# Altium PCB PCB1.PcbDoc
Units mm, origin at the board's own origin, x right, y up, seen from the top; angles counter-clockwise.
Board outline 152.4 x 101.6 mm, 2 copper layers (Top Layer, Bottom Layer); 306 components, 275 nets, 612 pads, 0 vias.
Unrouted connection lines stored in the file: 337.
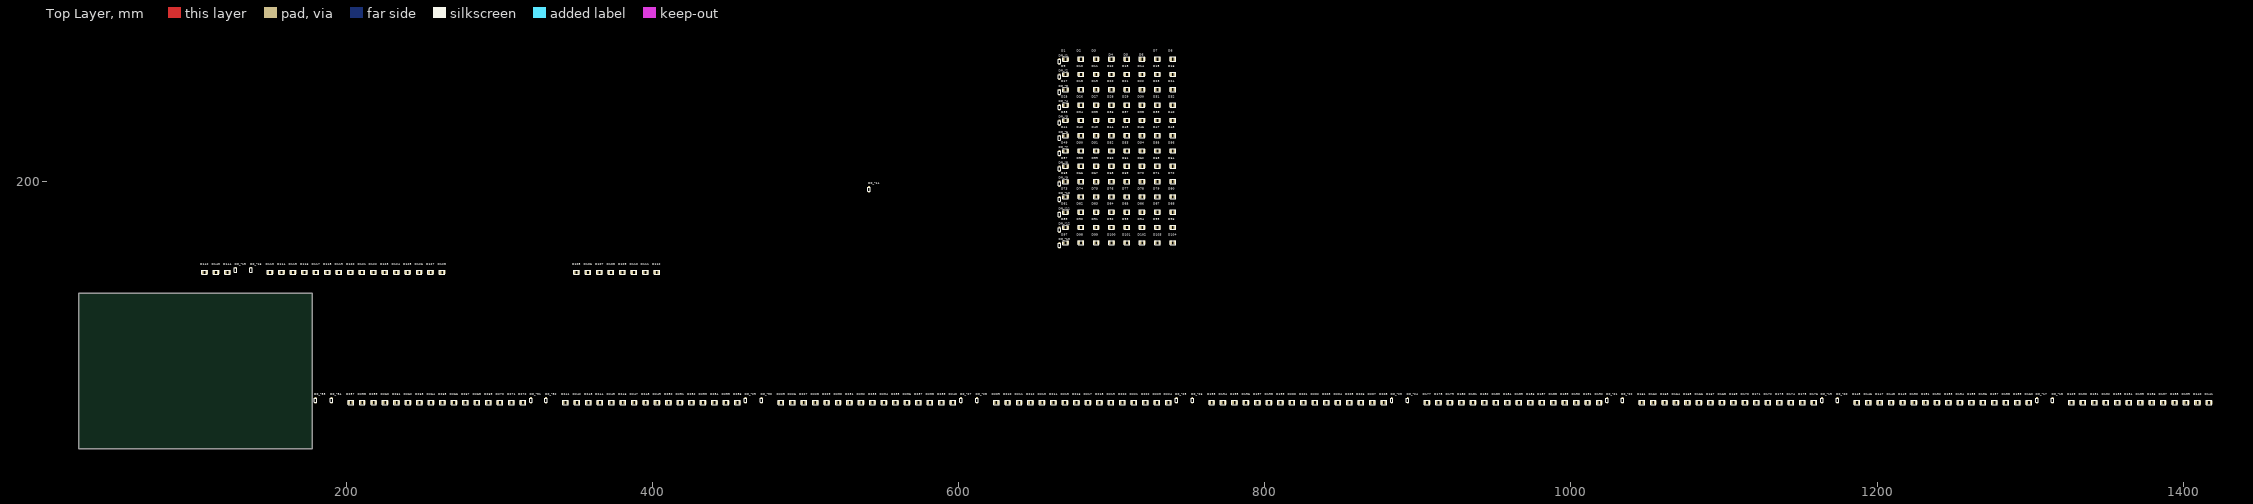
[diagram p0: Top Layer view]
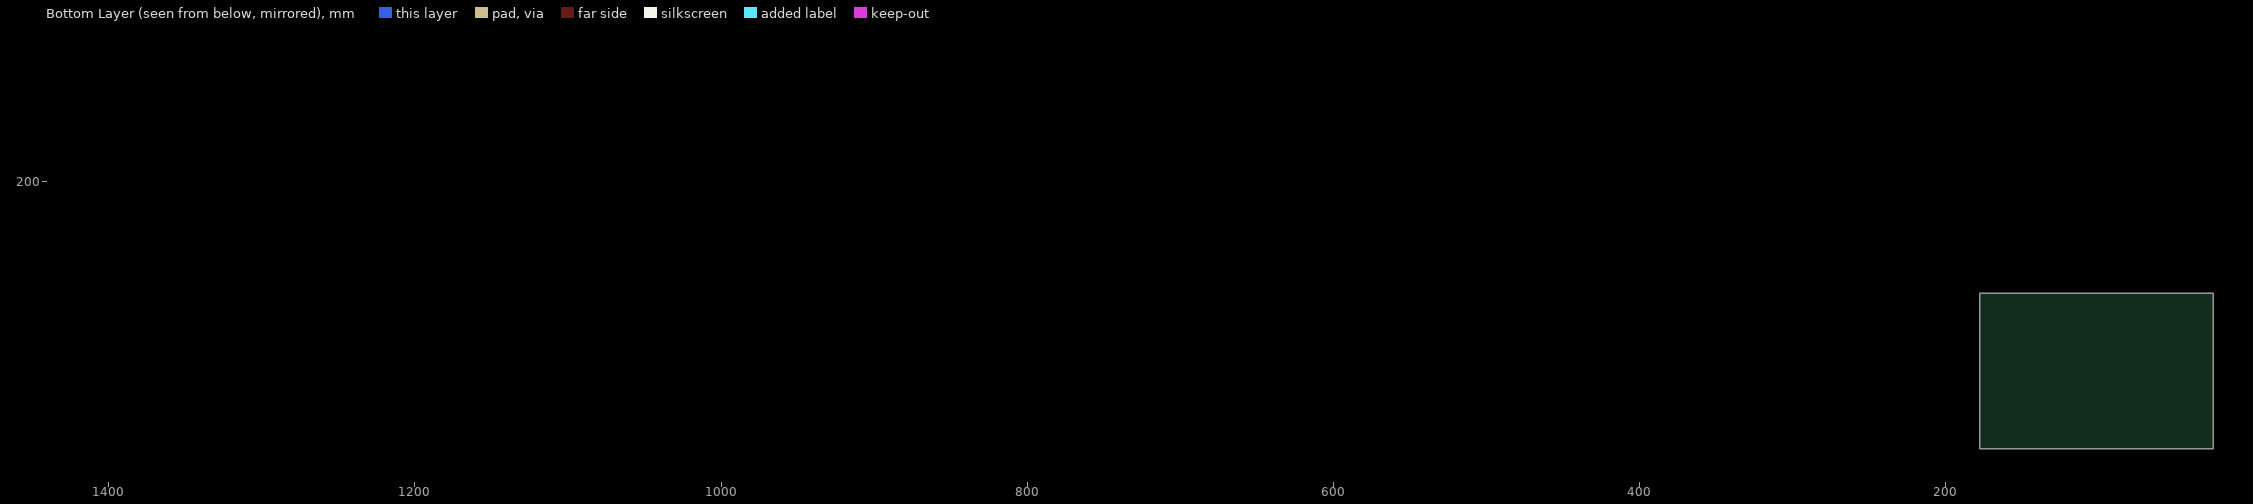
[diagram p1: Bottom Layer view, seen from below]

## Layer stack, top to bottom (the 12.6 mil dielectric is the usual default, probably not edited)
Top Solder: solder mask 0.0102, Solder Resist, Dk 3.5
Top Layer: signal copper 0.0356
Dielectric 1: dielectric 0.32, FR-4, Dk 4.8
Bottom Layer: signal copper 0.0356
Bottom Solder: solder mask 0.0102, Solder Resist, Dk 3.5

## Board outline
25.4,25.4 177.8,25.4 177.8,127 25.4,127

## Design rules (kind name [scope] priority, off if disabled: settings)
Clearance [All] p1: gap=0.254
PolygonConnect [All] p1: connectstyle=Relief reliefconductorwidth=0.254 reliefentries=4 polygonreliefangle="90 Angle" airgapwidth=0.254
RoutingVias [All] p1: holewidth=0.711 width=1.27 viastyle="Through Hole" minholewidth=0.711 minwidth=1.27 maxholewidth=0.711 maxwidth=1.27
SolderMaskExpansion [All] p1: expansion=0.102
Width [All] p1: maxlimit=0.254 minlimit=0.254 preferedwidth=0.254
30 further rules are at their usual default settings.

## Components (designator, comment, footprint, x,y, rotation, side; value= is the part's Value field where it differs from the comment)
D1 "LED0" UV_LED 670,280 r0 top
D2 "LED0" UV_LED 680,280 r0 top
D3 "LED0" UV_LED 690,280 r0 top
D4 "LED0" UV_LED 700,280 r0 top
D5 "LED0" UV_LED 710,280 r0 top
D6 "LED0" UV_LED 720,280 r0 top
D7 "LED0" UV_LED 730,280 r0 top
D8 "LED0" UV_LED 740,280 r0 top
D9 "LED0" UV_LED 670,270 r0 top
D10 "LED0" UV_LED 680,270 r0 top
D11 "LED0" UV_LED 690,270 r0 top
D12 "LED0" UV_LED 700,270 r0 top
D13 "LED0" UV_LED 710,270 r0 top
D14 "LED0" UV_LED 720,270 r0 top
D15 "LED0" UV_LED 730,270 r0 top
D16 "LED0" UV_LED 740,270 r0 top
D17 "LED0" UV_LED 670,260 r0 top
D18 "LED0" UV_LED 680,260 r0 top
D19 "LED0" UV_LED 690,260 r0 top
D20 "LED0" UV_LED 700,260 r0 top
D21 "LED0" UV_LED 710,260 r0 top
D22 "LED0" UV_LED 720,260 r0 top
D23 "LED0" UV_LED 730,260 r0 top
D24 "LED0" UV_LED 740,260 r0 top
D25 "LED0" UV_LED 670,250 r0 top
D26 "LED0" UV_LED 680,250 r0 top
D27 "LED0" UV_LED 690,250 r0 top
D28 "LED0" UV_LED 700,250 r0 top
D29 "LED0" UV_LED 710,250 r0 top
D30 "LED0" UV_LED 720,250 r0 top
D31 "LED0" UV_LED 730,250 r0 top
D32 "LED0" UV_LED 740,250 r0 top
D33 "LED0" UV_LED 670,240 r0 top
D34 "LED0" UV_LED 680,240 r0 top
D35 "LED0" UV_LED 690,240 r0 top
D36 "LED0" UV_LED 700,240 r0 top
D37 "LED0" UV_LED 710,240 r0 top
D38 "LED0" UV_LED 720,240 r0 top
D39 "LED0" UV_LED 730,240 r0 top
D40 "LED0" UV_LED 740,240 r0 top
D41 "LED0" UV_LED 670,230 r0 top
D42 "LED0" UV_LED 680,230 r0 top
D43 "LED0" UV_LED 690,230 r0 top
D44 "LED0" UV_LED 700,230 r0 top
D45 "LED0" UV_LED 710,230 r0 top
D46 "LED0" UV_LED 720,230 r0 top
D47 "LED0" UV_LED 730,230 r0 top
D48 "LED0" UV_LED 740,230 r0 top
D49 "LED0" UV_LED 670,220 r0 top
D50 "LED0" UV_LED 680,220 r0 top
D51 "LED0" UV_LED 690,220 r0 top
D52 "LED0" UV_LED 700,220 r0 top
D53 "LED0" UV_LED 710,220 r0 top
D54 "LED0" UV_LED 720,220 r0 top
D55 "LED0" UV_LED 730,220 r0 top
D56 "LED0" UV_LED 740,220 r0 top
D57 "LED0" UV_LED 670,210 r0 top
D58 "LED0" UV_LED 680,210 r0 top
D59 "LED0" UV_LED 690,210 r0 top
D60 "LED0" UV_LED 700,210 r0 top
D61 "LED0" UV_LED 710,210 r0 top
D62 "LED0" UV_LED 720,210 r0 top
D63 "LED0" UV_LED 730,210 r0 top
D64 "LED0" UV_LED 740,210 r0 top
D65 "LED0" UV_LED 670,200 r0 top
D66 "LED0" UV_LED 680,200 r0 top
D67 "LED0" UV_LED 690,200 r0 top
D68 "LED0" UV_LED 700,200 r0 top
D69 "LED0" UV_LED 710,200 r0 top
D70 "LED0" UV_LED 720,200 r0 top
D71 "LED0" UV_LED 730,200 r0 top
D72 "LED0" UV_LED 740,200 r0 top
D73 "LED0" UV_LED 670,190 r0 top
D74 "LED0" UV_LED 680,190 r0 top
D75 "LED0" UV_LED 690,190 r0 top
D76 "LED0" UV_LED 700,190 r0 top
D77 "LED0" UV_LED 710,190 r0 top
D78 "LED0" UV_LED 720,190 r0 top
D79 "LED0" UV_LED 730,190 r0 top
D80 "LED0" UV_LED 740,190 r0 top
D81 "LED0" UV_LED 670,180 r0 top
D82 "LED0" UV_LED 680,180 r0 top
D83 "LED0" UV_LED 690,180 r0 top
D84 "LED0" UV_LED 700,180 r0 top
D85 "LED0" UV_LED 710,180 r0 top
D86 "LED0" UV_LED 720,180 r0 top
D87 "LED0" UV_LED 730,180 r0 top
D88 "LED0" UV_LED 740,180 r0 top
D89 "LED0" UV_LED 670,170 r0 top
D90 "LED0" UV_LED 680,170 r0 top
D91 "LED0" UV_LED 690,170 r0 top
D92 "LED0" UV_LED 700,170 r0 top
D93 "LED0" UV_LED 710,170 r0 top
D94 "LED0" UV_LED 720,170 r0 top
D95 "LED0" UV_LED 730,170 r0 top
D96 "LED0" UV_LED 740,170 r0 top
D97 "LED0" UV_LED 670,160 r0 top
D98 "LED0" UV_LED 680,160 r0 top
D99 "LED0" UV_LED 690,160 r0 top
D100 "LED0" UV_LED 700,160 r0 top
D101 "LED0" UV_LED 710,160 r0 top
D102 "LED0" UV_LED 720,160 r0 top
D103 "LED0" UV_LED 730,160 r0 top
D104 "LED0" UV_LED 740,160 r0 top
D105 "LED0" UV_LED 350.52,140.716 r0 top
D106 "LED0" UV_LED 358.013,140.716 r0 top
D107 "LED0" UV_LED 365.506,140.716 r0 top
D108 "LED0" UV_LED 372.999,140.716 r0 top
D109 "LED0" UV_LED 380.492,140.716 r0 top
D110 "LED0" UV_LED 387.985,140.716 r0 top
D111 "LED0" UV_LED 395.478,140.716 r0 top
D112 "LED0" UV_LED 402.971,140.716 r0 top
D113 "LED0" UV_LED 150.368,140.716 r0 top
D114 "LED0" UV_LED 157.861,140.716 r0 top
D115 "LED0" UV_LED 165.354,140.716 r0 top
D116 "LED0" UV_LED 172.847,140.716 r0 top
D117 "LED0" UV_LED 180.34,140.716 r0 top
D118 "LED0" UV_LED 187.833,140.716 r0 top
D119 "LED0" UV_LED 195.326,140.716 r0 top
D120 "LED0" UV_LED 202.819,140.716 r0 top
D121 "LED0" UV_LED 210.312,140.716 r0 top
D122 "LED0" UV_LED 217.805,140.716 r0 top
D123 "LED0" UV_LED 225.298,140.716 r0 top
D124 "LED0" UV_LED 232.791,140.716 r0 top
D125 "LED0" UV_LED 240.284,140.716 r0 top
D126 "LED0" UV_LED 247.777,140.716 r0 top
D127 "LED0" UV_LED 255.27,140.716 r0 top
D128 "LED0" UV_LED 262.763,140.716 r0 top
D129 "LED0" UV_LED 1327.023,55.626 r0 top
D130 "LED0" UV_LED 1334.516,55.626 r0 top
D131 "LED0" UV_LED 1342.009,55.626 r0 top
D132 "LED0" UV_LED 1349.502,55.626 r0 top
D133 "LED0" UV_LED 1356.995,55.626 r0 top
D134 "LED0" UV_LED 1364.488,55.626 r0 top
D135 "LED0" UV_LED 1371.981,55.626 r0 top
D136 "LED0" UV_LED 1379.474,55.626 r0 top
D137 "LED0" UV_LED 1386.967,55.626 r0 top
D138 "LED0" UV_LED 1394.46,55.626 r0 top
D139 "LED0" UV_LED 1401.953,55.626 r0 top
D140 "LED0" UV_LED 1409.446,55.626 r0 top
D141 "LED0" UV_LED 1416.939,55.626 r0 top
D142 "LED0" UV_LED 107.569,140.716 r0 top
D143 "LED0" UV_LED 115.062,140.716 r0 top
D144 "LED0" UV_LED 122.555,140.716 r0 top
D145 "LED0" UV_LED 1186.815,55.626 r0 top
D146 "LED0" UV_LED 1194.308,55.626 r0 top
D147 "LED0" UV_LED 1201.801,55.626 r0 top
D148 "LED0" UV_LED 1209.294,55.626 r0 top
D149 "LED0" UV_LED 1216.787,55.626 r0 top
D150 "LED0" UV_LED 1224.28,55.626 r0 top
D151 "LED0" UV_LED 1231.773,55.626 r0 top
D152 "LED0" UV_LED 1239.266,55.626 r0 top
D153 "LED0" UV_LED 1246.759,55.626 r0 top
D154 "LED0" UV_LED 1254.252,55.626 r0 top
D155 "LED0" UV_LED 1261.745,55.626 r0 top
D156 "LED0" UV_LED 1269.238,55.626 r0 top
D157 "LED0" UV_LED 1276.731,55.626 r0 top
D158 "LED0" UV_LED 1284.224,55.626 r0 top
D159 "LED0" UV_LED 1291.717,55.626 r0 top
D160 "LED0" UV_LED 1299.21,55.626 r0 top
D161 "LED0" UV_LED 1046.353,55.626 r0 top
D162 "LED0" UV_LED 1053.846,55.626 r0 top
D163 "LED0" UV_LED 1061.339,55.626 r0 top
D164 "LED0" UV_LED 1068.832,55.626 r0 top
D165 "LED0" UV_LED 1076.325,55.626 r0 top
D166 "LED0" UV_LED 1083.818,55.626 r0 top
D167 "LED0" UV_LED 1091.311,55.626 r0 top
D168 "LED0" UV_LED 1098.804,55.626 r0 top
D169 "LED0" UV_LED 1106.297,55.626 r0 top
D170 "LED0" UV_LED 1113.79,55.626 r0 top
D171 "LED0" UV_LED 1121.283,55.626 r0 top
D172 "LED0" UV_LED 1128.776,55.626 r0 top
D173 "LED0" UV_LED 1136.269,55.626 r0 top
D174 "LED0" UV_LED 1143.762,55.626 r0 top
D175 "LED0" UV_LED 1151.255,55.626 r0 top
D176 "LED0" UV_LED 1158.748,55.626 r0 top
D177 "LED0" UV_LED 906.145,55.626 r0 top
D178 "LED0" UV_LED 913.638,55.626 r0 top
D179 "LED0" UV_LED 921.131,55.626 r0 top
D180 "LED0" UV_LED 928.624,55.626 r0 top
D181 "LED0" UV_LED 936.117,55.626 r0 top
D182 "LED0" UV_LED 943.61,55.626 r0 top
D183 "LED0" UV_LED 951.103,55.626 r0 top
D184 "LED0" UV_LED 958.596,55.626 r0 top
D185 "LED0" UV_LED 966.089,55.626 r0 top
D186 "LED0" UV_LED 973.582,55.626 r0 top
D187 "LED0" UV_LED 981.075,55.626 r0 top
D188 "LED0" UV_LED 988.568,55.626 r0 top
D189 "LED0" UV_LED 996.061,55.626 r0 top
D190 "LED0" UV_LED 1003.554,55.626 r0 top
D191 "LED0" UV_LED 1011.047,55.626 r0 top
D192 "LED0" UV_LED 1018.54,55.626 r0 top
D193 "LED0" UV_LED 765.429,55.626 r0 top
D194 "LED0" UV_LED 772.922,55.626 r0 top
D195 "LED0" UV_LED 780.415,55.626 r0 top
D196 "LED0" UV_LED 787.908,55.626 r0 top
D197 "LED0" UV_LED 795.401,55.626 r0 top
D198 "LED0" UV_LED 802.894,55.626 r0 top
D199 "LED0" UV_LED 810.387,55.626 r0 top
D200 "LED0" UV_LED 817.88,55.626 r0 top
D201 "LED0" UV_LED 825.373,55.626 r0 top
D202 "LED0" UV_LED 832.866,55.626 r0 top
D203 "LED0" UV_LED 840.359,55.626 r0 top
D204 "LED0" UV_LED 847.852,55.626 r0 top
D205 "LED0" UV_LED 855.345,55.626 r0 top
D206 "LED0" UV_LED 862.838,55.626 r0 top
D207 "LED0" UV_LED 870.331,55.626 r0 top
D208 "LED0" UV_LED 877.824,55.626 r0 top
D209 "LED0" UV_LED 624.713,55.626 r0 top
D210 "LED0" UV_LED 632.206,55.626 r0 top
D211 "LED0" UV_LED 639.699,55.626 r0 top
D212 "LED0" UV_LED 647.192,55.626 r0 top
D213 "LED0" UV_LED 654.685,55.626 r0 top
D214 "LED0" UV_LED 662.178,55.626 r0 top
D215 "LED0" UV_LED 669.671,55.626 r0 top
D216 "LED0" UV_LED 677.164,55.626 r0 top
D217 "LED0" UV_LED 684.657,55.626 r0 top
D218 "LED0" UV_LED 692.15,55.626 r0 top
D219 "LED0" UV_LED 699.643,55.626 r0 top
D220 "LED0" UV_LED 707.136,55.626 r0 top
D221 "LED0" UV_LED 714.629,55.626 r0 top
D222 "LED0" UV_LED 722.122,55.626 r0 top
D223 "LED0" UV_LED 729.615,55.626 r0 top
D224 "LED0" UV_LED 737.108,55.626 r0 top
D225 "LED0" UV_LED 483.997,55.626 r0 top
D226 "LED0" UV_LED 491.49,55.626 r0 top
D227 "LED0" UV_LED 498.983,55.626 r0 top
D228 "LED0" UV_LED 506.476,55.626 r0 top
D229 "LED0" UV_LED 513.969,55.626 r0 top
D230 "LED0" UV_LED 521.462,55.626 r0 top
D231 "LED0" UV_LED 528.955,55.626 r0 top
D232 "LED0" UV_LED 536.448,55.626 r0 top
D233 "LED0" UV_LED 543.941,55.626 r0 top
D234 "LED0" UV_LED 551.434,55.626 r0 top
D235 "LED0" UV_LED 558.927,55.626 r0 top
D236 "LED0" UV_LED 566.42,55.626 r0 top
D237 "LED0" UV_LED 573.913,55.626 r0 top
D238 "LED0" UV_LED 581.406,55.626 r0 top
D239 "LED0" UV_LED 588.899,55.626 r0 top
D240 "LED0" UV_LED 596.392,55.626 r0 top
D241 "LED0" UV_LED 343.281,55.626 r0 top
D242 "LED0" UV_LED 350.774,55.626 r0 top
D243 "LED0" UV_LED 358.267,55.626 r0 top
D244 "LED0" UV_LED 365.76,55.626 r0 top
D245 "LED0" UV_LED 373.253,55.626 r0 top
D246 "LED0" UV_LED 380.746,55.626 r0 top
D247 "LED0" UV_LED 388.239,55.626 r0 top
D248 "LED0" UV_LED 395.732,55.626 r0 top
D249 "LED0" UV_LED 403.225,55.626 r0 top
D250 "LED0" UV_LED 410.718,55.626 r0 top
D251 "LED0" UV_LED 418.211,55.626 r0 top
D252 "LED0" UV_LED 425.704,55.626 r0 top
D253 "LED0" UV_LED 433.197,55.626 r0 top
D254 "LED0" UV_LED 440.69,55.626 r0 top
D255 "LED0" UV_LED 448.183,55.626 r0 top
D256 "LED0" UV_LED 455.676,55.626 r0 top
D257 "LED0" UV_LED 203.073,55.626 r0 top
D258 "LED0" UV_LED 210.566,55.626 r0 top
D259 "LED0" UV_LED 218.059,55.626 r0 top
D260 "LED0" UV_LED 225.552,55.626 r0 top
D261 "LED0" UV_LED 233.045,55.626 r0 top
D262 "LED0" UV_LED 240.538,55.626 r0 top
D263 "LED0" UV_LED 248.031,55.626 r0 top
D264 "LED0" UV_LED 255.524,55.626 r0 top
D265 "LED0" UV_LED 263.017,55.626 r0 top
D266 "LED0" UV_LED 270.51,55.626 r0 top
D267 "LED0" UV_LED 278.003,55.626 r0 top
D268 "LED0" UV_LED 285.496,55.626 r0 top
D269 "LED0" UV_LED 292.989,55.626 r0 top
D270 "LED0" UV_LED 300.482,55.626 r0 top
D271 "LED0" UV_LED 307.975,55.626 r0 top
D272 "LED0" UV_LED 315.468,55.626 r0 top
DR_*1 "NSI45020AT1G" NSI45020AT1G 665.988,278.365 r90 top
DR_*2 "NSI45020AT1G" NSI45020AT1G 665.988,268.365 r90 top
DR_*3 "NSI45020AT1G" NSI45020AT1G 665.988,258.365 r90 top
DR_*4 "NSI45020AT1G" NSI45020AT1G 665.988,248.365 r90 top
DR_*5 "NSI45020AT1G" NSI45020AT1G 665.988,238.365 r90 top
DR_*6 "NSI45020AT1G" NSI45020AT1G 665.988,228.365 r90 top
DR_*7 "NSI45020AT1G" NSI45020AT1G 665.988,218.365 r90 top
DR_*8 "NSI45020AT1G" NSI45020AT1G 665.988,208.365 r90 top
DR_*9 "NSI45020AT1G" NSI45020AT1G 665.988,198.365 r90 top
DR_*10 "NSI45020AT1G" NSI45020AT1G 665.988,188.365 r90 top
DR_*11 "NSI45020AT1G" NSI45020AT1G 665.988,178.365 r90 top
DR_*12 "NSI45020AT1G" NSI45020AT1G 665.988,168.365 r90 top
DR_*13 "NSI45020AT1G" NSI45020AT1G 665.988,158.365 r90 top
DR_*14 "NSI45020AT1G" NSI45020AT1G 541.528,194.945 r90 top
DR_*15 "NSI45020AT1G" NSI45020AT1G 127.762,142.113 r90 top
DR_*16 "NSI45020AT1G" NSI45020AT1G 137.922,142.113 r90 top
DR_*17 "NSI45020AT1G" NSI45020AT1G 1304.417,57.023 r90 top
DR_*18 "NSI45020AT1G" NSI45020AT1G 1314.577,57.023 r90 top
DR_*19 "NSI45020AT1G" NSI45020AT1G 1163.955,57.023 r90 top
DR_*20 "NSI45020AT1G" NSI45020AT1G 1174.115,57.023 r90 top
DR_*21 "NSI45020AT1G" NSI45020AT1G 1023.747,57.023 r90 top
DR_*22 "NSI45020AT1G" NSI45020AT1G 1033.653,57.023 r90 top
DR_*23 "NSI45020AT1G" NSI45020AT1G 883.031,57.023 r90 top
DR_*24 "NSI45020AT1G" NSI45020AT1G 893.445,57.023 r90 top
DR_*25 "NSI45020AT1G" NSI45020AT1G 742.315,57.023 r90 top
DR_*26 "NSI45020AT1G" NSI45020AT1G 752.729,57.023 r90 top
DR_*27 "NSI45020AT1G" NSI45020AT1G 601.599,57.023 r90 top
DR_*28 "NSI45020AT1G" NSI45020AT1G 612.013,57.023 r90 top
DR_*29 "NSI45020AT1G" NSI45020AT1G 460.883,57.023 r90 top
DR_*30 "NSI45020AT1G" NSI45020AT1G 471.297,57.023 r90 top
DR_*31 "NSI45020AT1G" NSI45020AT1G 320.675,57.023 r90 top
DR_*32 "NSI45020AT1G" NSI45020AT1G 330.581,57.023 r90 top
DR_*33 "NSI45020AT1G" NSI45020AT1G 179.959,57.023 r90 top
DR_*34 "NSI45020AT1G" NSI45020AT1G 190.373,57.023 r90 top

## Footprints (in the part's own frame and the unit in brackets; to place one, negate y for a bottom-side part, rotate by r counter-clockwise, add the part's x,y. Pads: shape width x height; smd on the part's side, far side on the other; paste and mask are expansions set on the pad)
NSI45020AT1G [mm]
  rect 0.91x1.22 smd: A(-1.635,0) K(1.635,0)
  silkscreen extent -1.35,-0.8 1.35,0.8
UV_LED [mm]
  rect 1.5x2.6 smd: 1(-1.35,0) 2(1.35,0)
  silkscreen extent -1.78,-1.4 1.78,1.4

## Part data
D1 D2 D3 D4 D5 D6 D7 D8 D9 D10 D11 D12 D13 D14 D15 D16 D17 D18 D19 D20 D21 D22 D23 D24 D25 D26 D27 D28 D29 D30 D31 D32 D33 D34 D35 D36 D37 D38 D39 D40 D41 D42 D43 D44 D45 D46 D47 D48 D49 D50 D51 D52 D53 D54 D55 D56 D57 D58 D59 D60 D61 D62 D63 D64 D65 D66 D67 D68 D69 D70 D71 D72 D73 D74 D75 D76 D77 D78 D79 D80 D81 D82 D83 D84 D85 D86 D87 D88 D89 D90 D91 D92 D93 D94 D95 D96 D97 D98 D99 D100 D101 D102 D103 D104 D105 D106 D107 D108 D109 D110 D111 D112 D113 D114 D115 D116 D117 D118 D119 D120 D121 D122 D123 D124 D125 D126 D127 D128 D129 D130 D131 D132 D133 D134 D135 D136 D137 D138 D139 D140 D141 D142 D143 D144 D145 D146 D147 D148 D149 D150 D151 D152 D153 D154 D155 D156 D157 D158 D159 D160 D161 D162 D163 D164 D165 D166 D167 D168 D169 D170 D171 D172 D173 D174 D175 D176 D177 D178 D179 D180 D181 D182 D183 D184 D185 D186 D187 D188 D189 D190 D191 D192 D193 D194 D195 D196 D197 D198 D199 D200 D201 D202 D203 D204 D205 D206 D207 D208 D209 D210 D211 D212 D213 D214 D215 D216 D217 D218 D219 D220 D221 D222 D223 D224 D225 D226 D227 D228 D229 D230 D231 D232 D233 D234 D235 D236 D237 D238 D239 D240 D241 D242 D243 D244 D245 D246 D247 D248 D249 D250 D251 D252 D253 D254 D255 D256 D257 D258 D259 D260 D261 D262 D263 D264 D265 D266 D267 D268 D269 D270 D271 D272: "Typical INFRARED GaAs LED"

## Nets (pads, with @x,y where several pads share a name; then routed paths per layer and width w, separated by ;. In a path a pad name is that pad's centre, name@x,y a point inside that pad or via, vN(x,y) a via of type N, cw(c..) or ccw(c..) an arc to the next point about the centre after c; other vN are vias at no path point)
GND: D8.2 D16.2 D24.2 D32.2 D40.2 D48.2 D56.2 D64.2 D72.2 D80.2 D88.2 D96.2 D104.2 D112.2 D120.2 D128.2 D136.2 D144.2 D152.2 D160.2 D168.2 D176.2 D184.2 D192.2 D200.2 D208.2 D216.2 D224.2 D232.2 D240.2 D248.2 D256.2 D264.2 D272.2
NetD1_1: D1.1 DR_*1.K
NetD1_2: D1.2 D2.1
NetD2_2: D2.2 D3.1
NetD3_2: D3.2 D4.1
NetD4_2: D4.2 D5.1
NetD5_2: D5.2 D6.1
NetD6_2: D6.2 D7.1
NetD7_2: D7.2 D8.1
NetD9_1: D9.1 DR_*2.K
NetD9_2: D9.2 D10.1
NetD10_2: D10.2 D11.1
NetD11_2: D11.2 D12.1
NetD12_2: D12.2 D13.1
NetD13_2: D13.2 D14.1
NetD14_2: D14.2 D15.1
NetD15_2: D15.2 D16.1
NetD17_1: D17.1 DR_*3.K
NetD17_2: D17.2 D18.1
NetD18_2: D18.2 D19.1
NetD19_2: D19.2 D20.1
NetD20_2: D20.2 D21.1
NetD21_2: D21.2 D22.1
NetD22_2: D22.2 D23.1
NetD23_2: D23.2 D24.1
NetD25_1: D25.1 DR_*4.K
NetD25_2: D25.2 D26.1
NetD26_2: D26.2 D27.1
NetD27_2: D27.2 D28.1
NetD28_2: D28.2 D29.1
NetD29_2: D29.2 D30.1
NetD30_2: D30.2 D31.1
NetD31_2: D31.2 D32.1
NetD33_1: D33.1 DR_*5.K
NetD33_2: D33.2 D34.1
NetD34_2: D34.2 D35.1
NetD35_2: D35.2 D36.1
NetD36_2: D36.2 D37.1
NetD37_2: D37.2 D38.1
NetD38_2: D38.2 D39.1
NetD39_2: D39.2 D40.1
NetD41_1: D41.1 DR_*6.K
NetD41_2: D41.2 D42.1
NetD42_2: D42.2 D43.1
NetD43_2: D43.2 D44.1
NetD44_2: D44.2 D45.1
NetD45_2: D45.2 D46.1
NetD46_2: D46.2 D47.1
NetD47_2: D47.2 D48.1
NetD49_1: D49.1 DR_*7.K
NetD49_2: D49.2 D50.1
NetD50_2: D50.2 D51.1
NetD51_2: D51.2 D52.1
NetD52_2: D52.2 D53.1
NetD53_2: D53.2 D54.1
NetD54_2: D54.2 D55.1
NetD55_2: D55.2 D56.1
NetD57_1: D57.1 DR_*8.K
NetD57_2: D57.2 D58.1
NetD58_2: D58.2 D59.1
NetD59_2: D59.2 D60.1
NetD60_2: D60.2 D61.1
NetD61_2: D61.2 D62.1
NetD62_2: D62.2 D63.1
NetD63_2: D63.2 D64.1
NetD65_1: D65.1 DR_*9.K
NetD65_2: D65.2 D66.1
NetD66_2: D66.2 D67.1
NetD67_2: D67.2 D68.1
NetD68_2: D68.2 D69.1
NetD69_2: D69.2 D70.1
NetD70_2: D70.2 D71.1
NetD71_2: D71.2 D72.1
NetD73_1: D73.1 DR_*10.K
NetD73_2: D73.2 D74.1
NetD74_2: D74.2 D75.1
NetD75_2: D75.2 D76.1
NetD76_2: D76.2 D77.1
NetD77_2: D77.2 D78.1
NetD78_2: D78.2 D79.1
NetD79_2: D79.2 D80.1
NetD81_1: D81.1 DR_*11.K
NetD81_2: D81.2 D82.1
NetD82_2: D82.2 D83.1
NetD83_2: D83.2 D84.1
NetD84_2: D84.2 D85.1
NetD85_2: D85.2 D86.1
NetD86_2: D86.2 D87.1
NetD87_2: D87.2 D88.1
NetD89_1: D89.1 DR_*12.K
NetD89_2: D89.2 D90.1
NetD90_2: D90.2 D91.1
NetD91_2: D91.2 D92.1
NetD92_2: D92.2 D93.1
NetD93_2: D93.2 D94.1
NetD94_2: D94.2 D95.1
NetD95_2: D95.2 D96.1
NetD97_1: D97.1 DR_*13.K
NetD97_2: D97.2 D98.1
NetD98_2: D98.2 D99.1
NetD99_2: D99.2 D100.1
NetD100_2: D100.2 D101.1
NetD101_2: D101.2 D102.1
NetD102_2: D102.2 D103.1
NetD103_2: D103.2 D104.1
NetD105_1: D105.1 DR_*14.K
NetD105_2: D105.2 D106.1
NetD106_2: D106.2 D107.1
NetD107_2: D107.2 D108.1
NetD108_2: D108.2 D109.1
NetD109_2: D109.2 D110.1
NetD110_2: D110.2 D111.1
NetD111_2: D111.2 D112.1
NetD113_1: D113.1 DR_*15.K
NetD113_2: D113.2 D114.1
NetD114_2: D114.2 D115.1
NetD115_2: D115.2 D116.1
NetD116_2: D116.2 D117.1
NetD117_2: D117.2 D118.1
NetD118_2: D118.2 D119.1
NetD119_2: D119.2 D120.1
NetD121_1: D121.1 DR_*16.K
NetD121_2: D121.2 D122.1
NetD122_2: D122.2 D123.1
NetD123_2: D123.2 D124.1
NetD124_2: D124.2 D125.1
NetD125_2: D125.2 D126.1
NetD126_2: D126.2 D127.1
NetD127_2: D127.2 D128.1
NetD129_1: D129.1 DR_*17.K
NetD129_2: D129.2 D130.1
NetD130_2: D130.2 D131.1
NetD131_2: D131.2 D132.1
NetD132_2: D132.2 D133.1
NetD133_2: D133.2 D134.1
NetD134_2: D134.2 D135.1
NetD135_2: D135.2 D136.1
NetD137_1: D137.1 DR_*18.K
NetD137_2: D137.2 D138.1
NetD138_2: D138.2 D139.1
NetD139_2: D139.2 D140.1
NetD140_2: D140.2 D141.1
NetD141_2: D141.2 D142.1
NetD142_2: D142.2 D143.1
NetD143_2: D143.2 D144.1
NetD145_1: D145.1 DR_*19.K
NetD145_2: D145.2 D146.1
NetD146_2: D146.2 D147.1
NetD147_2: D147.2 D148.1
NetD148_2: D148.2 D149.1
NetD149_2: D149.2 D150.1
NetD150_2: D150.2 D151.1
NetD151_2: D151.2 D152.1
NetD153_1: D153.1 DR_*20.K
NetD153_2: D153.2 D154.1
NetD154_2: D154.2 D155.1
NetD155_2: D155.2 D156.1
NetD156_2: D156.2 D157.1
NetD157_2: D157.2 D158.1
NetD158_2: D158.2 D159.1
NetD159_2: D159.2 D160.1
NetD161_1: D161.1 DR_*21.K
NetD161_2: D161.2 D162.1
NetD162_2: D162.2 D163.1
NetD163_2: D163.2 D164.1
NetD164_2: D164.2 D165.1
NetD165_2: D165.2 D166.1
NetD166_2: D166.2 D167.1
NetD167_2: D167.2 D168.1
NetD169_1: D169.1 DR_*22.K
NetD169_2: D169.2 D170.1
NetD170_2: D170.2 D171.1
NetD171_2: D171.2 D172.1
NetD172_2: D172.2 D173.1
NetD173_2: D173.2 D174.1
NetD174_2: D174.2 D175.1
NetD175_2: D175.2 D176.1
NetD177_1: D177.1 DR_*23.K
NetD177_2: D177.2 D178.1
NetD178_2: D178.2 D179.1
NetD179_2: D179.2 D180.1
NetD180_2: D180.2 D181.1
NetD181_2: D181.2 D182.1
NetD182_2: D182.2 D183.1
NetD183_2: D183.2 D184.1
NetD185_1: D185.1 DR_*24.K
NetD185_2: D185.2 D186.1
NetD186_2: D186.2 D187.1
NetD187_2: D187.2 D188.1
NetD188_2: D188.2 D189.1
NetD189_2: D189.2 D190.1
NetD190_2: D190.2 D191.1
NetD191_2: D191.2 D192.1
NetD193_1: D193.1 DR_*25.K
NetD193_2: D193.2 D194.1
NetD194_2: D194.2 D195.1
NetD195_2: D195.2 D196.1
NetD196_2: D196.2 D197.1
NetD197_2: D197.2 D198.1
NetD198_2: D198.2 D199.1
NetD199_2: D199.2 D200.1
NetD201_1: D201.1 DR_*26.K
NetD201_2: D201.2 D202.1
NetD202_2: D202.2 D203.1
NetD203_2: D203.2 D204.1
NetD204_2: D204.2 D205.1
NetD205_2: D205.2 D206.1
NetD206_2: D206.2 D207.1
NetD207_2: D207.2 D208.1
NetD209_1: D209.1 DR_*27.K
NetD209_2: D209.2 D210.1
NetD210_2: D210.2 D211.1
NetD211_2: D211.2 D212.1
NetD212_2: D212.2 D213.1
NetD213_2: D213.2 D214.1
NetD214_2: D214.2 D215.1
NetD215_2: D215.2 D216.1
NetD217_1: D217.1 DR_*28.K
NetD217_2: D217.2 D218.1
NetD218_2: D218.2 D219.1
NetD219_2: D219.2 D220.1
NetD220_2: D220.2 D221.1
NetD221_2: D221.2 D222.1
NetD222_2: D222.2 D223.1
NetD223_2: D223.2 D224.1
NetD225_1: D225.1 DR_*29.K
NetD225_2: D225.2 D226.1
NetD226_2: D226.2 D227.1
NetD227_2: D227.2 D228.1
NetD228_2: D228.2 D229.1
NetD229_2: D229.2 D230.1
NetD230_2: D230.2 D231.1
NetD231_2: D231.2 D232.1
NetD233_1: D233.1 DR_*30.K
NetD233_2: D233.2 D234.1
NetD234_2: D234.2 D235.1
NetD235_2: D235.2 D236.1
NetD236_2: D236.2 D237.1
NetD237_2: D237.2 D238.1
NetD238_2: D238.2 D239.1
NetD239_2: D239.2 D240.1
NetD241_1: D241.1 DR_*31.K
NetD241_2: D241.2 D242.1
NetD242_2: D242.2 D243.1
NetD243_2: D243.2 D244.1
NetD244_2: D244.2 D245.1
NetD245_2: D245.2 D246.1
NetD246_2: D246.2 D247.1
NetD247_2: D247.2 D248.1
NetD249_1: D249.1 DR_*32.K
NetD249_2: D249.2 D250.1
NetD250_2: D250.2 D251.1
NetD251_2: D251.2 D252.1
NetD252_2: D252.2 D253.1
NetD253_2: D253.2 D254.1
NetD254_2: D254.2 D255.1
NetD255_2: D255.2 D256.1
NetD257_1: D257.1 DR_*33.K
NetD257_2: D257.2 D258.1
NetD258_2: D258.2 D259.1
NetD259_2: D259.2 D260.1
NetD260_2: D260.2 D261.1
NetD261_2: D261.2 D262.1
NetD262_2: D262.2 D263.1
NetD263_2: D263.2 D264.1
NetD265_1: D265.1 DR_*34.K
NetD265_2: D265.2 D266.1
NetD266_2: D266.2 D267.1
NetD267_2: D267.2 D268.1
NetD268_2: D268.2 D269.1
NetD269_2: D269.2 D270.1
NetD270_2: D270.2 D271.1
NetD271_2: D271.2 D272.1
VCC_1: DR_*1.A DR_*2.A DR_*3.A DR_*4.A DR_*5.A DR_*6.A DR_*7.A DR_*8.A DR_*9.A DR_*10.A DR_*11.A DR_*12.A DR_*13.A
VCC_2: DR_*14.A DR_*15.A DR_*16.A DR_*17.A DR_*18.A DR_*19.A DR_*20.A DR_*21.A DR_*22.A DR_*23.A DR_*24.A DR_*25.A DR_*26.A DR_*27.A DR_*28.A DR_*29.A DR_*30.A DR_*31.A DR_*32.A DR_*33.A DR_*34.A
